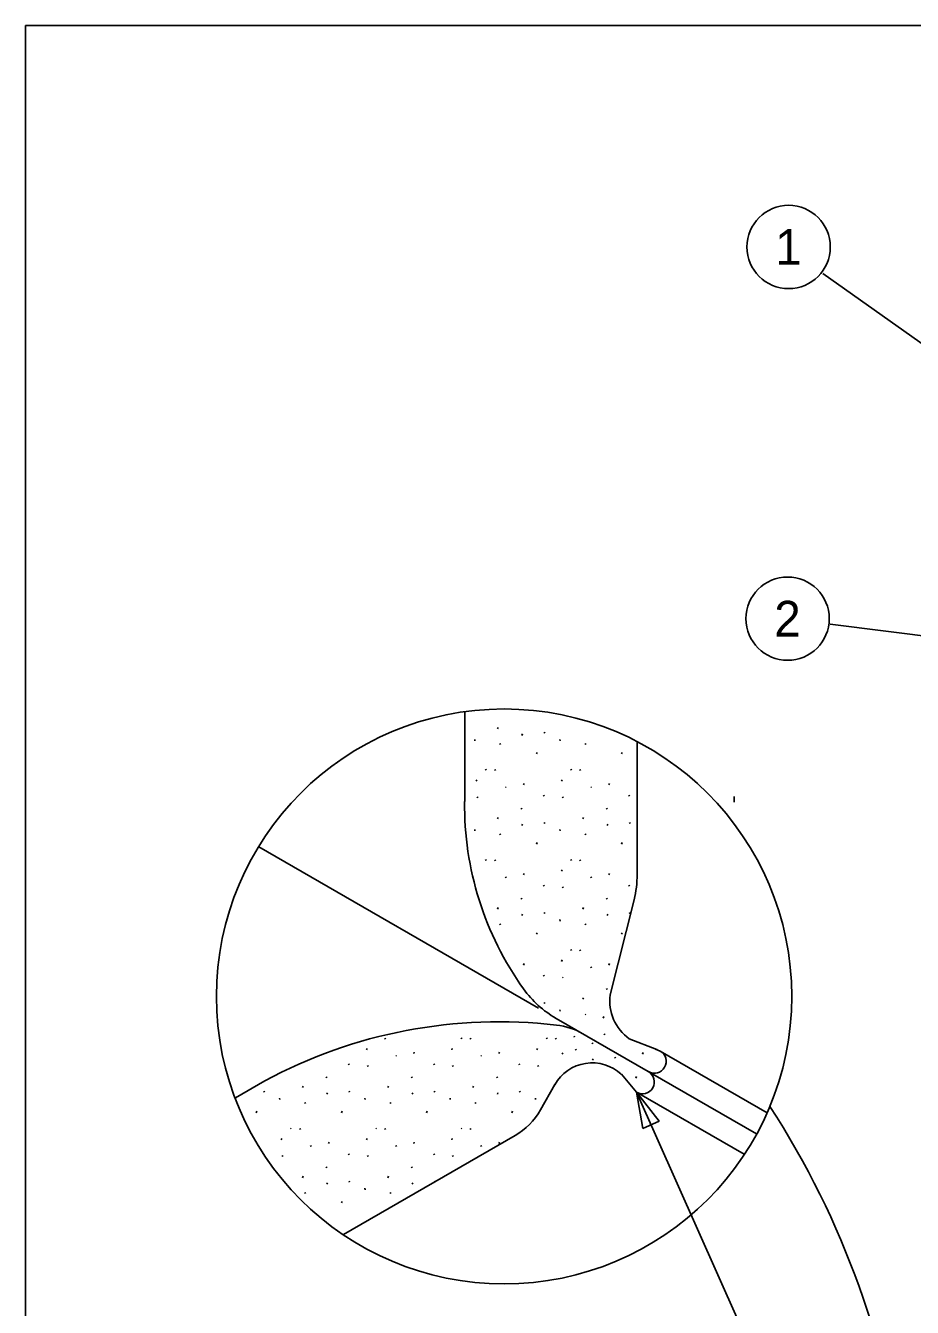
# Model space of a CAD drawing. Extents: x 10110.2 to 10159.4, y 10049.5 to 10140.5.
# Drawn here: x 10110.22 to 10126.8, y 10116.52 to 10140.51 of the extents above; entities that cross this region are included whole.
import ezdxf

# ---------------------------------------------------------------- set-up
doc = ezdxf.new("R2010")
doc.units = 0
for name, color, linetype in [('G-ANNO-SYMB', 7, 'Continuous'), ('G-DETL-GRID', 7, 'Continuous'), ('G-DETL-LINE', 7, 'Continuous'), ('G-DETL-TEXT', 7, 'Continuous')]:
    doc.layers.add(name, color=color, linetype=linetype)

msp = doc.modelspace()

# ---------------------------------------------------------------- linework, layer by layer
at = {"layer": 'G-ANNO-SYMB'}
for centre in [(10124.483, 10136.364), (10124.464, 10129.41)]:
    msp.add_circle(centre, 0.779, dxfattribs=at)
at = {"layer": 'G-DETL-GRID'}
msp.add_lwpolyline([(10110.22, 10140.505), (10159.362, 10140.505), (10159.362, 10095.005), (10110.22, 10095.005)], close=True, dxfattribs=at)
at = {"layer": 'G-DETL-LINE'}
for p, q in [((10118.427, 10127.663), (10118.427, 10125.989)), ((10118.427, 10127.663), (10118.427, 10125.989)), ((10119.04, 10127.349), (10119.052, 10127.376)), ((10119.04, 10127.349), (10119.052, 10127.376)), ((10118.614, 10127.151), (10118.617, 10127.124)), ((10118.614, 10127.151), (10118.617, 10127.124)), ((10119.495, 10127.226), (10119.507, 10127.253)), ((10119.495, 10127.226), (10119.507, 10127.253)), ((10119.911, 10127.285), (10119.923, 10127.267)), ((10119.911, 10127.285), (10119.923, 10127.267)), ((10120.208, 10127.151), (10120.211, 10127.124)), ((10120.208, 10127.151), (10120.211, 10127.124)), ((10119.083, 10127.072), (10119.095, 10127.054)), ((10119.083, 10127.072), (10119.095, 10127.054)), ((10119.768, 10126.879), (10119.78, 10126.906)), ((10119.768, 10126.879), (10119.78, 10126.906)), ((10120.678, 10127.072), (10120.69, 10127.054)), ((10120.678, 10127.072), (10120.69, 10127.054)), ((10121.362, 10126.879), (10121.374, 10126.906)), ((10121.362, 10126.879), (10121.374, 10126.906)), ((10121.652, 10127.102), (10121.652, 10124.624)), ((10121.652, 10127.102), (10121.652, 10124.624)), ((10118.641, 10126.37), (10118.653, 10126.397)), ((10118.641, 10126.37), (10118.653, 10126.397)), ((10118.818, 10126.592), (10118.83, 10126.574)), ((10118.818, 10126.592), (10118.83, 10126.574)), ((10118.989, 10126.586), (10119.001, 10126.568)), ((10118.989, 10126.586), (10119.001, 10126.568)), ((10120.236, 10126.37), (10120.248, 10126.397)), ((10120.236, 10126.37), (10120.248, 10126.397)), ((10120.413, 10126.592), (10120.425, 10126.574)), ((10120.413, 10126.592), (10120.425, 10126.574)), ((10120.583, 10126.586), (10120.595, 10126.568)), ((10120.583, 10126.586), (10120.595, 10126.568)), ((10119.19, 10126.266), (10119.202, 10126.248)), ((10119.19, 10126.266), (10119.202, 10126.248)), ((10119.525, 10126.301), (10119.537, 10126.328)), ((10119.525, 10126.301), (10119.537, 10126.328)), ((10120.784, 10126.266), (10120.796, 10126.248)), ((10120.784, 10126.266), (10120.796, 10126.248)), ((10121.12, 10126.301), (10121.132, 10126.328)), ((10121.12, 10126.301), (10121.132, 10126.328)), ((10118.66, 10126.077), (10118.672, 10126.059)), ((10118.66, 10126.077), (10118.672, 10126.059)), ((10119.9, 10126.11), (10119.912, 10126.092)), ((10119.9, 10126.11), (10119.912, 10126.092)), ((10120.254, 10126.077), (10120.266, 10126.059)), ((10120.254, 10126.077), (10120.266, 10126.059)), ((10121.494, 10126.11), (10121.506, 10126.092)), ((10121.494, 10126.11), (10121.506, 10126.092)), ((10123.463, 10126.082), (10123.463, 10125.978)), ((10123.463, 10126.082), (10123.463, 10125.978)), ((10119.04, 10125.663), (10119.052, 10125.69)), ((10119.04, 10125.663), (10119.052, 10125.69)), ((10119.486, 10125.864), (10119.498, 10125.846)), ((10119.486, 10125.864), (10119.498, 10125.846)), ((10120.634, 10125.663), (10120.646, 10125.69)), ((10120.634, 10125.663), (10120.646, 10125.69)), ((10121.08, 10125.864), (10121.092, 10125.846)), ((10121.08, 10125.864), (10121.092, 10125.846)), ((10118.614, 10125.465), (10118.617, 10125.438)), ((10118.614, 10125.465), (10118.617, 10125.438)), ((10119.495, 10125.54), (10119.507, 10125.567)), ((10119.495, 10125.54), (10119.507, 10125.567)), ((10119.911, 10125.598), (10119.923, 10125.58)), ((10119.911, 10125.598), (10119.923, 10125.58)), ((10120.208, 10125.465), (10120.211, 10125.438)), ((10120.208, 10125.465), (10120.211, 10125.438)), ((10121.09, 10125.54), (10121.102, 10125.567)), ((10121.09, 10125.54), (10121.102, 10125.567)), ((10121.506, 10125.598), (10121.518, 10125.58)), ((10121.506, 10125.598), (10121.518, 10125.58)), ((10119.083, 10125.385), (10119.095, 10125.367)), ((10119.083, 10125.385), (10119.095, 10125.367)), ((10119.768, 10125.192), (10119.78, 10125.219)), ((10119.768, 10125.192), (10119.78, 10125.219)), ((10120.678, 10125.385), (10120.69, 10125.367)), ((10120.678, 10125.385), (10120.69, 10125.367)), ((10121.362, 10125.192), (10121.374, 10125.219)), ((10121.362, 10125.192), (10121.374, 10125.219)), ((10114.578, 10125.141), (10119.81, 10122.12)), ((10114.578, 10125.141), (10119.81, 10122.12)), ((10118.818, 10124.906), (10118.83, 10124.888)), ((10118.818, 10124.906), (10118.83, 10124.888)), ((10118.989, 10124.899), (10119.001, 10124.881)), ((10118.989, 10124.899), (10119.001, 10124.881)), ((10120.236, 10124.684), (10120.248, 10124.711)), ((10120.236, 10124.684), (10120.248, 10124.711)), ((10120.413, 10124.906), (10120.425, 10124.888)), ((10120.413, 10124.906), (10120.425, 10124.888)), ((10120.583, 10124.899), (10120.595, 10124.881)), ((10120.583, 10124.899), (10120.595, 10124.881)), ((10119.19, 10124.58), (10119.202, 10124.562)), ((10119.19, 10124.58), (10119.202, 10124.562)), ((10119.525, 10124.615), (10119.537, 10124.642)), ((10119.525, 10124.615), (10119.537, 10124.642)), ((10120.784, 10124.58), (10120.796, 10124.562)), ((10120.784, 10124.58), (10120.796, 10124.562)), ((10121.12, 10124.615), (10121.132, 10124.642)), ((10121.12, 10124.615), (10121.132, 10124.642)), ((10119.9, 10124.423), (10119.912, 10124.405)), ((10119.9, 10124.423), (10119.912, 10124.405)), ((10120.254, 10124.391), (10120.266, 10124.373)), ((10120.254, 10124.391), (10120.266, 10124.373)), ((10121.494, 10124.423), (10121.506, 10124.405)), ((10121.494, 10124.423), (10121.506, 10124.405)), ((10119.04, 10123.977), (10119.052, 10124.004)), ((10119.04, 10123.977), (10119.052, 10124.004)), ((10119.486, 10124.178), (10119.498, 10124.16)), ((10119.486, 10124.178), (10119.498, 10124.16)), ((10120.634, 10123.977), (10120.646, 10124.004)), ((10120.634, 10123.977), (10120.646, 10124.004)), ((10121.08, 10124.178), (10121.092, 10124.16)), ((10121.08, 10124.178), (10121.092, 10124.16)), ((10121.146, 10122.373), (10121.594, 10124.151)), ((10121.146, 10122.373), (10121.594, 10124.151)), ((10119.495, 10123.854), (10119.507, 10123.881)), ((10119.495, 10123.854), (10119.507, 10123.881)), ((10119.911, 10123.912), (10119.923, 10123.894)), ((10119.911, 10123.912), (10119.923, 10123.894)), ((10120.208, 10123.779), (10120.211, 10123.752)), ((10120.208, 10123.779), (10120.211, 10123.752)), ((10121.09, 10123.854), (10121.102, 10123.881)), ((10121.09, 10123.854), (10121.102, 10123.881)), ((10121.506, 10123.912), (10121.517, 10123.894)), ((10121.506, 10123.912), (10121.517, 10123.894)), ((10119.083, 10123.699), (10119.095, 10123.681)), ((10119.083, 10123.699), (10119.095, 10123.681)), ((10119.768, 10123.506), (10119.78, 10123.533)), ((10119.768, 10123.506), (10119.78, 10123.533)), ((10120.678, 10123.699), (10120.69, 10123.681)), ((10120.678, 10123.699), (10120.69, 10123.681)), ((10121.362, 10123.506), (10121.374, 10123.533)), ((10121.362, 10123.506), (10121.374, 10123.533)), ((10120.413, 10123.22), (10120.425, 10123.202)), ((10120.413, 10123.22), (10120.425, 10123.202)), ((10120.583, 10123.213), (10120.595, 10123.195)), ((10120.583, 10123.213), (10120.595, 10123.195)), ((10119.525, 10122.929), (10119.537, 10122.956)), ((10119.525, 10122.929), (10119.537, 10122.956)), ((10120.236, 10122.998), (10120.248, 10123.025)), ((10120.236, 10122.998), (10120.248, 10123.025)), ((10120.784, 10122.894), (10120.796, 10122.876)), ((10120.784, 10122.894), (10120.796, 10122.876)), ((10121.12, 10122.929), (10121.132, 10122.956)), ((10121.12, 10122.929), (10121.132, 10122.956)), ((10119.9, 10122.737), (10119.912, 10122.719)), ((10119.9, 10122.737), (10119.912, 10122.719)), ((10120.254, 10122.705), (10120.266, 10122.687)), ((10120.254, 10122.705), (10120.266, 10122.687)), ((10120.634, 10122.29), (10120.646, 10122.317)), ((10120.634, 10122.29), (10120.646, 10122.317)), ((10121.08, 10122.492), (10121.092, 10122.474)), ((10121.08, 10122.492), (10121.092, 10122.474)), ((10119.911, 10122.226), (10119.923, 10122.208)), ((10119.911, 10122.226), (10119.923, 10122.208)), ((10120.208, 10122.092), (10120.211, 10122.065)), ((10120.208, 10122.092), (10120.211, 10122.065)), ((10121.652, 10121.056), (10120.135, 10121.932)), ((10121.652, 10121.056), (10120.135, 10121.932)), ((10120.678, 10122.013), (10120.69, 10121.995)), ((10120.678, 10122.013), (10120.69, 10121.995)), ((10121.014, 10121.937), (10121.026, 10121.964)), ((10121.014, 10121.937), (10121.026, 10121.964)), ((10120.471, 10121.598), (10120.483, 10121.58)), ((10120.471, 10121.598), (10120.483, 10121.58)), ((10121.033, 10121.643), (10121.045, 10121.625)), ((10121.033, 10121.643), (10121.045, 10121.625)), ((10116.59, 10121.344), (10116.602, 10121.371)), ((10116.59, 10121.344), (10116.602, 10121.371)), ((10116.937, 10121.559), (10116.949, 10121.541)), ((10116.937, 10121.559), (10116.949, 10121.541)), ((10118.184, 10121.344), (10118.196, 10121.371)), ((10118.184, 10121.344), (10118.196, 10121.371)), ((10118.361, 10121.566), (10118.373, 10121.548)), ((10118.361, 10121.566), (10118.373, 10121.548)), ((10118.531, 10121.559), (10118.543, 10121.541)), ((10118.531, 10121.559), (10118.543, 10121.541)), ((10119.778, 10121.344), (10119.79, 10121.371)), ((10119.778, 10121.344), (10119.79, 10121.371)), ((10119.955, 10121.566), (10119.967, 10121.548)), ((10119.955, 10121.566), (10119.967, 10121.548)), ((10120.126, 10121.559), (10120.138, 10121.541)), ((10120.126, 10121.559), (10120.138, 10121.541)), ((10120.5, 10121.357), (10120.512, 10121.339)), ((10120.5, 10121.357), (10120.512, 10121.339)), ((10120.809, 10121.471), (10120.821, 10121.453)), ((10120.809, 10121.471), (10120.821, 10121.453)), ((10122.019, 10121.348), (10121.504, 10121.549)), ((10122.019, 10121.348), (10121.504, 10121.549)), ((10122.083, 10121.319), (10121.997, 10121.357)), ((10122.083, 10121.319), (10121.997, 10121.357)), ((10117.138, 10121.24), (10117.15, 10121.222)), ((10117.138, 10121.24), (10117.15, 10121.222)), ((10117.474, 10121.275), (10117.486, 10121.302)), ((10117.474, 10121.275), (10117.486, 10121.302)), ((10118.732, 10121.24), (10118.744, 10121.222)), ((10118.732, 10121.24), (10118.744, 10121.222)), ((10119.068, 10121.275), (10119.08, 10121.302)), ((10119.068, 10121.275), (10119.08, 10121.302)), ((10120.25, 10121.261), (10120.262, 10121.288)), ((10120.25, 10121.261), (10120.262, 10121.288)), ((10120.818, 10121.147), (10120.83, 10121.173)), ((10120.818, 10121.147), (10120.83, 10121.173)), ((10121.234, 10121.205), (10121.246, 10121.187)), ((10121.234, 10121.205), (10121.246, 10121.187)), ((10121.753, 10121.264), (10121.765, 10121.291)), ((10121.753, 10121.264), (10121.765, 10121.291)), ((10124.081, 10120.166), (10122.083, 10121.319)), ((10124.081, 10120.166), (10122.083, 10121.319)), ((10116.254, 10121.083), (10116.266, 10121.065)), ((10116.254, 10121.083), (10116.266, 10121.065)), ((10116.608, 10121.051), (10116.62, 10121.033)), ((10116.608, 10121.051), (10116.62, 10121.033)), ((10117.848, 10121.083), (10117.86, 10121.065)), ((10117.848, 10121.083), (10117.86, 10121.065)), ((10118.202, 10121.051), (10118.214, 10121.033)), ((10118.202, 10121.051), (10118.214, 10121.033)), ((10119.443, 10121.083), (10119.455, 10121.065)), ((10119.443, 10121.083), (10119.455, 10121.065)), ((10119.797, 10121.051), (10119.809, 10121.033)), ((10119.797, 10121.051), (10119.809, 10121.033)), ((10121.356, 10120.885), (10121.64, 10120.551)), ((10121.356, 10120.885), (10121.64, 10120.551)), ((10123.881, 10119.77), (10121.652, 10121.056)), ((10123.881, 10119.77), (10121.652, 10121.056)), ((10114.689, 10120.76), (10114.14, 10120.444)), ((10114.689, 10120.76), (10114.14, 10120.444)), ((10115.394, 10120.637), (10115.406, 10120.664)), ((10115.394, 10120.637), (10115.406, 10120.664)), ((10115.839, 10120.838), (10115.851, 10120.82)), ((10115.839, 10120.838), (10115.851, 10120.82)), ((10116.988, 10120.637), (10117, 10120.664)), ((10116.988, 10120.637), (10117, 10120.664)), ((10117.434, 10120.838), (10117.446, 10120.82)), ((10117.434, 10120.838), (10117.446, 10120.82)), ((10118.582, 10120.637), (10118.594, 10120.664)), ((10118.582, 10120.637), (10118.594, 10120.664)), ((10119.028, 10120.838), (10119.04, 10120.82)), ((10119.028, 10120.838), (10119.04, 10120.82)), ((10119.846, 10120.22), (10120.115, 10120.696)), ((10119.846, 10120.22), (10120.115, 10120.696)), ((10121.627, 10120.816), (10121.639, 10120.843)), ((10121.627, 10120.816), (10121.639, 10120.843)), ((10114.671, 10120.572), (10114.683, 10120.554)), ((10114.671, 10120.572), (10114.683, 10120.554)), ((10114.968, 10120.438), (10114.971, 10120.411)), ((10114.968, 10120.438), (10114.971, 10120.411)), ((10115.849, 10120.514), (10115.861, 10120.541)), ((10115.849, 10120.514), (10115.861, 10120.541)), ((10116.265, 10120.572), (10116.277, 10120.554)), ((10116.265, 10120.572), (10116.277, 10120.554)), ((10116.562, 10120.438), (10116.565, 10120.411)), ((10116.562, 10120.438), (10116.565, 10120.411)), ((10117.444, 10120.514), (10117.456, 10120.541)), ((10117.444, 10120.514), (10117.456, 10120.541)), ((10117.859, 10120.572), (10117.871, 10120.554)), ((10117.859, 10120.572), (10117.871, 10120.554)), ((10118.156, 10120.438), (10118.159, 10120.411)), ((10118.156, 10120.438), (10118.159, 10120.411)), ((10119.038, 10120.514), (10119.05, 10120.541)), ((10119.038, 10120.514), (10119.05, 10120.541)), ((10119.454, 10120.572), (10119.466, 10120.554)), ((10119.454, 10120.572), (10119.466, 10120.554)), ((10119.751, 10120.438), (10119.754, 10120.411)), ((10119.751, 10120.438), (10119.754, 10120.411)), ((10123.651, 10119.39), (10121.64, 10120.551)), ((10123.651, 10119.39), (10121.64, 10120.551)), ((10114.528, 10120.166), (10114.54, 10120.193)), ((10114.528, 10120.166), (10114.54, 10120.193)), ((10115.437, 10120.359), (10115.449, 10120.341)), ((10115.437, 10120.359), (10115.449, 10120.341)), ((10116.122, 10120.166), (10116.134, 10120.193)), ((10116.122, 10120.166), (10116.134, 10120.193)), ((10117.032, 10120.359), (10117.044, 10120.341)), ((10117.032, 10120.359), (10117.044, 10120.341)), ((10117.716, 10120.166), (10117.728, 10120.193)), ((10117.716, 10120.166), (10117.728, 10120.193)), ((10118.626, 10120.359), (10118.638, 10120.341)), ((10118.626, 10120.359), (10118.638, 10120.341)), ((10119.311, 10120.166), (10119.323, 10120.193)), ((10119.311, 10120.166), (10119.323, 10120.193)), ((10114.995, 10119.658), (10115.007, 10119.685)), ((10114.995, 10119.658), (10115.007, 10119.685)), ((10115.172, 10119.88), (10115.184, 10119.862)), ((10115.172, 10119.88), (10115.184, 10119.862)), ((10115.343, 10119.873), (10115.355, 10119.855)), ((10115.343, 10119.873), (10115.355, 10119.855)), ((10119.368, 10119.738), (10116.163, 10117.887)), ((10119.368, 10119.738), (10116.163, 10117.887)), ((10116.59, 10119.658), (10116.602, 10119.685)), ((10116.59, 10119.658), (10116.602, 10119.685)), ((10116.766, 10119.88), (10116.778, 10119.862)), ((10116.766, 10119.88), (10116.778, 10119.862)), ((10116.937, 10119.873), (10116.949, 10119.855)), ((10116.937, 10119.873), (10116.949, 10119.855)), ((10118.184, 10119.658), (10118.196, 10119.685)), ((10118.184, 10119.658), (10118.196, 10119.685)), ((10118.361, 10119.88), (10118.373, 10119.862)), ((10118.361, 10119.88), (10118.373, 10119.862)), ((10118.531, 10119.873), (10118.543, 10119.855)), ((10118.531, 10119.873), (10118.543, 10119.855)), ((10115.544, 10119.554), (10115.556, 10119.536)), ((10115.544, 10119.554), (10115.556, 10119.536)), ((10115.879, 10119.589), (10115.891, 10119.616)), ((10115.879, 10119.589), (10115.891, 10119.616)), ((10117.138, 10119.554), (10117.15, 10119.536)), ((10117.138, 10119.554), (10117.15, 10119.536)), ((10117.474, 10119.589), (10117.486, 10119.616)), ((10117.474, 10119.589), (10117.486, 10119.616)), ((10118.732, 10119.554), (10118.744, 10119.536)), ((10118.732, 10119.554), (10118.744, 10119.536)), ((10119.068, 10119.589), (10119.08, 10119.616)), ((10119.068, 10119.589), (10119.08, 10119.616)), ((10115.014, 10119.364), (10115.026, 10119.346)), ((10115.014, 10119.364), (10115.026, 10119.346)), ((10116.254, 10119.397), (10116.266, 10119.379)), ((10116.254, 10119.397), (10116.266, 10119.379)), ((10116.608, 10119.364), (10116.62, 10119.346)), ((10116.608, 10119.364), (10116.62, 10119.346)), ((10117.848, 10119.397), (10117.86, 10119.379)), ((10117.848, 10119.397), (10117.86, 10119.379)), ((10118.202, 10119.364), (10118.214, 10119.346)), ((10118.202, 10119.364), (10118.214, 10119.346)), ((10115.394, 10118.95), (10115.406, 10118.977)), ((10115.394, 10118.95), (10115.406, 10118.977)), ((10115.839, 10119.152), (10115.851, 10119.134)), ((10115.839, 10119.152), (10115.851, 10119.134)), ((10116.988, 10118.95), (10117, 10118.977)), ((10116.988, 10118.95), (10117, 10118.977)), ((10117.434, 10119.152), (10117.446, 10119.134)), ((10117.434, 10119.152), (10117.446, 10119.134)), ((10115.849, 10118.827), (10115.861, 10118.854)), ((10115.849, 10118.827), (10115.861, 10118.854)), ((10116.265, 10118.886), (10116.277, 10118.868)), ((10116.265, 10118.886), (10116.277, 10118.868)), ((10116.562, 10118.752), (10116.565, 10118.725)), ((10116.562, 10118.752), (10116.565, 10118.725)), ((10117.444, 10118.827), (10117.456, 10118.854)), ((10117.444, 10118.827), (10117.456, 10118.854)), ((10117.859, 10118.886), (10117.869, 10118.872)), ((10117.859, 10118.886), (10117.869, 10118.872)), ((10115.437, 10118.673), (10115.449, 10118.655)), ((10115.437, 10118.673), (10115.449, 10118.655)), ((10116.122, 10118.48), (10116.134, 10118.507)), ((10116.122, 10118.48), (10116.134, 10118.507)), ((10117.032, 10118.673), (10117.044, 10118.655)), ((10117.032, 10118.673), (10117.044, 10118.655))]:
    msp.add_line(p, q, dxfattribs=at)
msp.add_circle((10119.164, 10122.342), 5.378, dxfattribs=at)
msp.add_circle((10119.164, 10122.342), 5.378, dxfattribs=at)
for centre, radius, start, end in [((10124.325, 10125.916), 5.899, 179.2851, 215.6022), ((10124.325, 10125.916), 5.899, 179.2851, 215.6022), ((10119.717, 10124.624), 1.935, 345.8569, 0), ((10119.717, 10124.624), 1.935, 345.8569, 0), ((10121.102, 10123.608), 1.935, 215.6022, 240.0001), ((10121.102, 10123.608), 1.935, 215.6022, 240.0001), ((10122.013, 10122.26), 0.874, 172.6182, 234.4112), ((10122.013, 10122.26), 0.874, 172.6182, 234.4112), ((10119.069, 10112.658), 9.211, 83.3014, 118.3969), ((10119.069, 10112.658), 9.211, 83.3014, 118.3969), ((10119.993, 10120.525), 1.29, 60.0002, 83.3014), ((10119.993, 10120.525), 1.29, 60.0002, 83.3014), ((10121.973, 10121.127), 0.222, 239.9993, 59.9993), ((10121.973, 10121.127), 0.222, 239.9993, 59.9993), ((10120.81, 10120.3), 0.8, 47.0339, 150.7736), ((10120.81, 10120.3), 0.8, 47.0339, 150.7736), ((10121.751, 10120.743), 0.222, 239.9993, 59.9993), ((10121.751, 10120.743), 0.222, 239.9993, 59.9993), ((10118.723, 10120.855), 1.29, 300, 330.5386), ((10118.723, 10120.855), 1.29, 300, 330.5386)]:
    msp.add_arc(centre, radius, start, end, dxfattribs=at)
at = {"layer": 'G-DETL-TEXT'}
for p, q in [((10125.12, 10135.869), (10127.462, 10134.206)), ((10125.258, 10129.309), (10131.765, 10128.489)), ((10125.258, 10129.309), (10131.765, 10128.489)), ((10123.54, 10116.28), (10121.64, 10120.551))]:
    msp.add_line(p, q, dxfattribs=at)
msp.add_lwpolyline([(10121.759, 10119.874), (10121.64, 10120.551), (10122.063, 10120.01)], close=True, dxfattribs=at)
msp.add_lwpolyline([(10121.759, 10119.874), (10121.64, 10120.551), (10122.063, 10120.01)], close=True, dxfattribs=at)
msp.add_arc((10110.325, 10111.351), 16.446, 340.7432, 32.9017, dxfattribs=at)

# ---------------------------------------------------------------- texts
at = {"layer": 'G-ANNO-SYMB'}
for s, p in [('1', (10124.233, 10136.031)), ('2', (10124.214, 10129.076))]:
    msp.add_text(s, height=0.667, dxfattribs=at).set_placement(p)

doc.saveas('drawing.dxf')
